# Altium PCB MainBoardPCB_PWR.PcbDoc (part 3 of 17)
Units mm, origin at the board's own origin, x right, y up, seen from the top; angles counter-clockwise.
Board outline 333.63 x 349.38 mm, 16 copper layers (L1, L2 (GND), L3 (Sign), L4 (GND), L5 (Sign), L6 (PWR/GND), L7(PWR/GND), L8 (PWR/GND), L9 (PWR/GND), L10 (PWR/GND), L11 (PWR/GND), L12 (Sign), L13 (GND), L14 (Sign), L15 (GND), L16), stack 2.503 mm thick; 2187 components, 1615 nets, 7987 pads, 1695 vias.
Unrouted connection lines stored in the file: 4757.
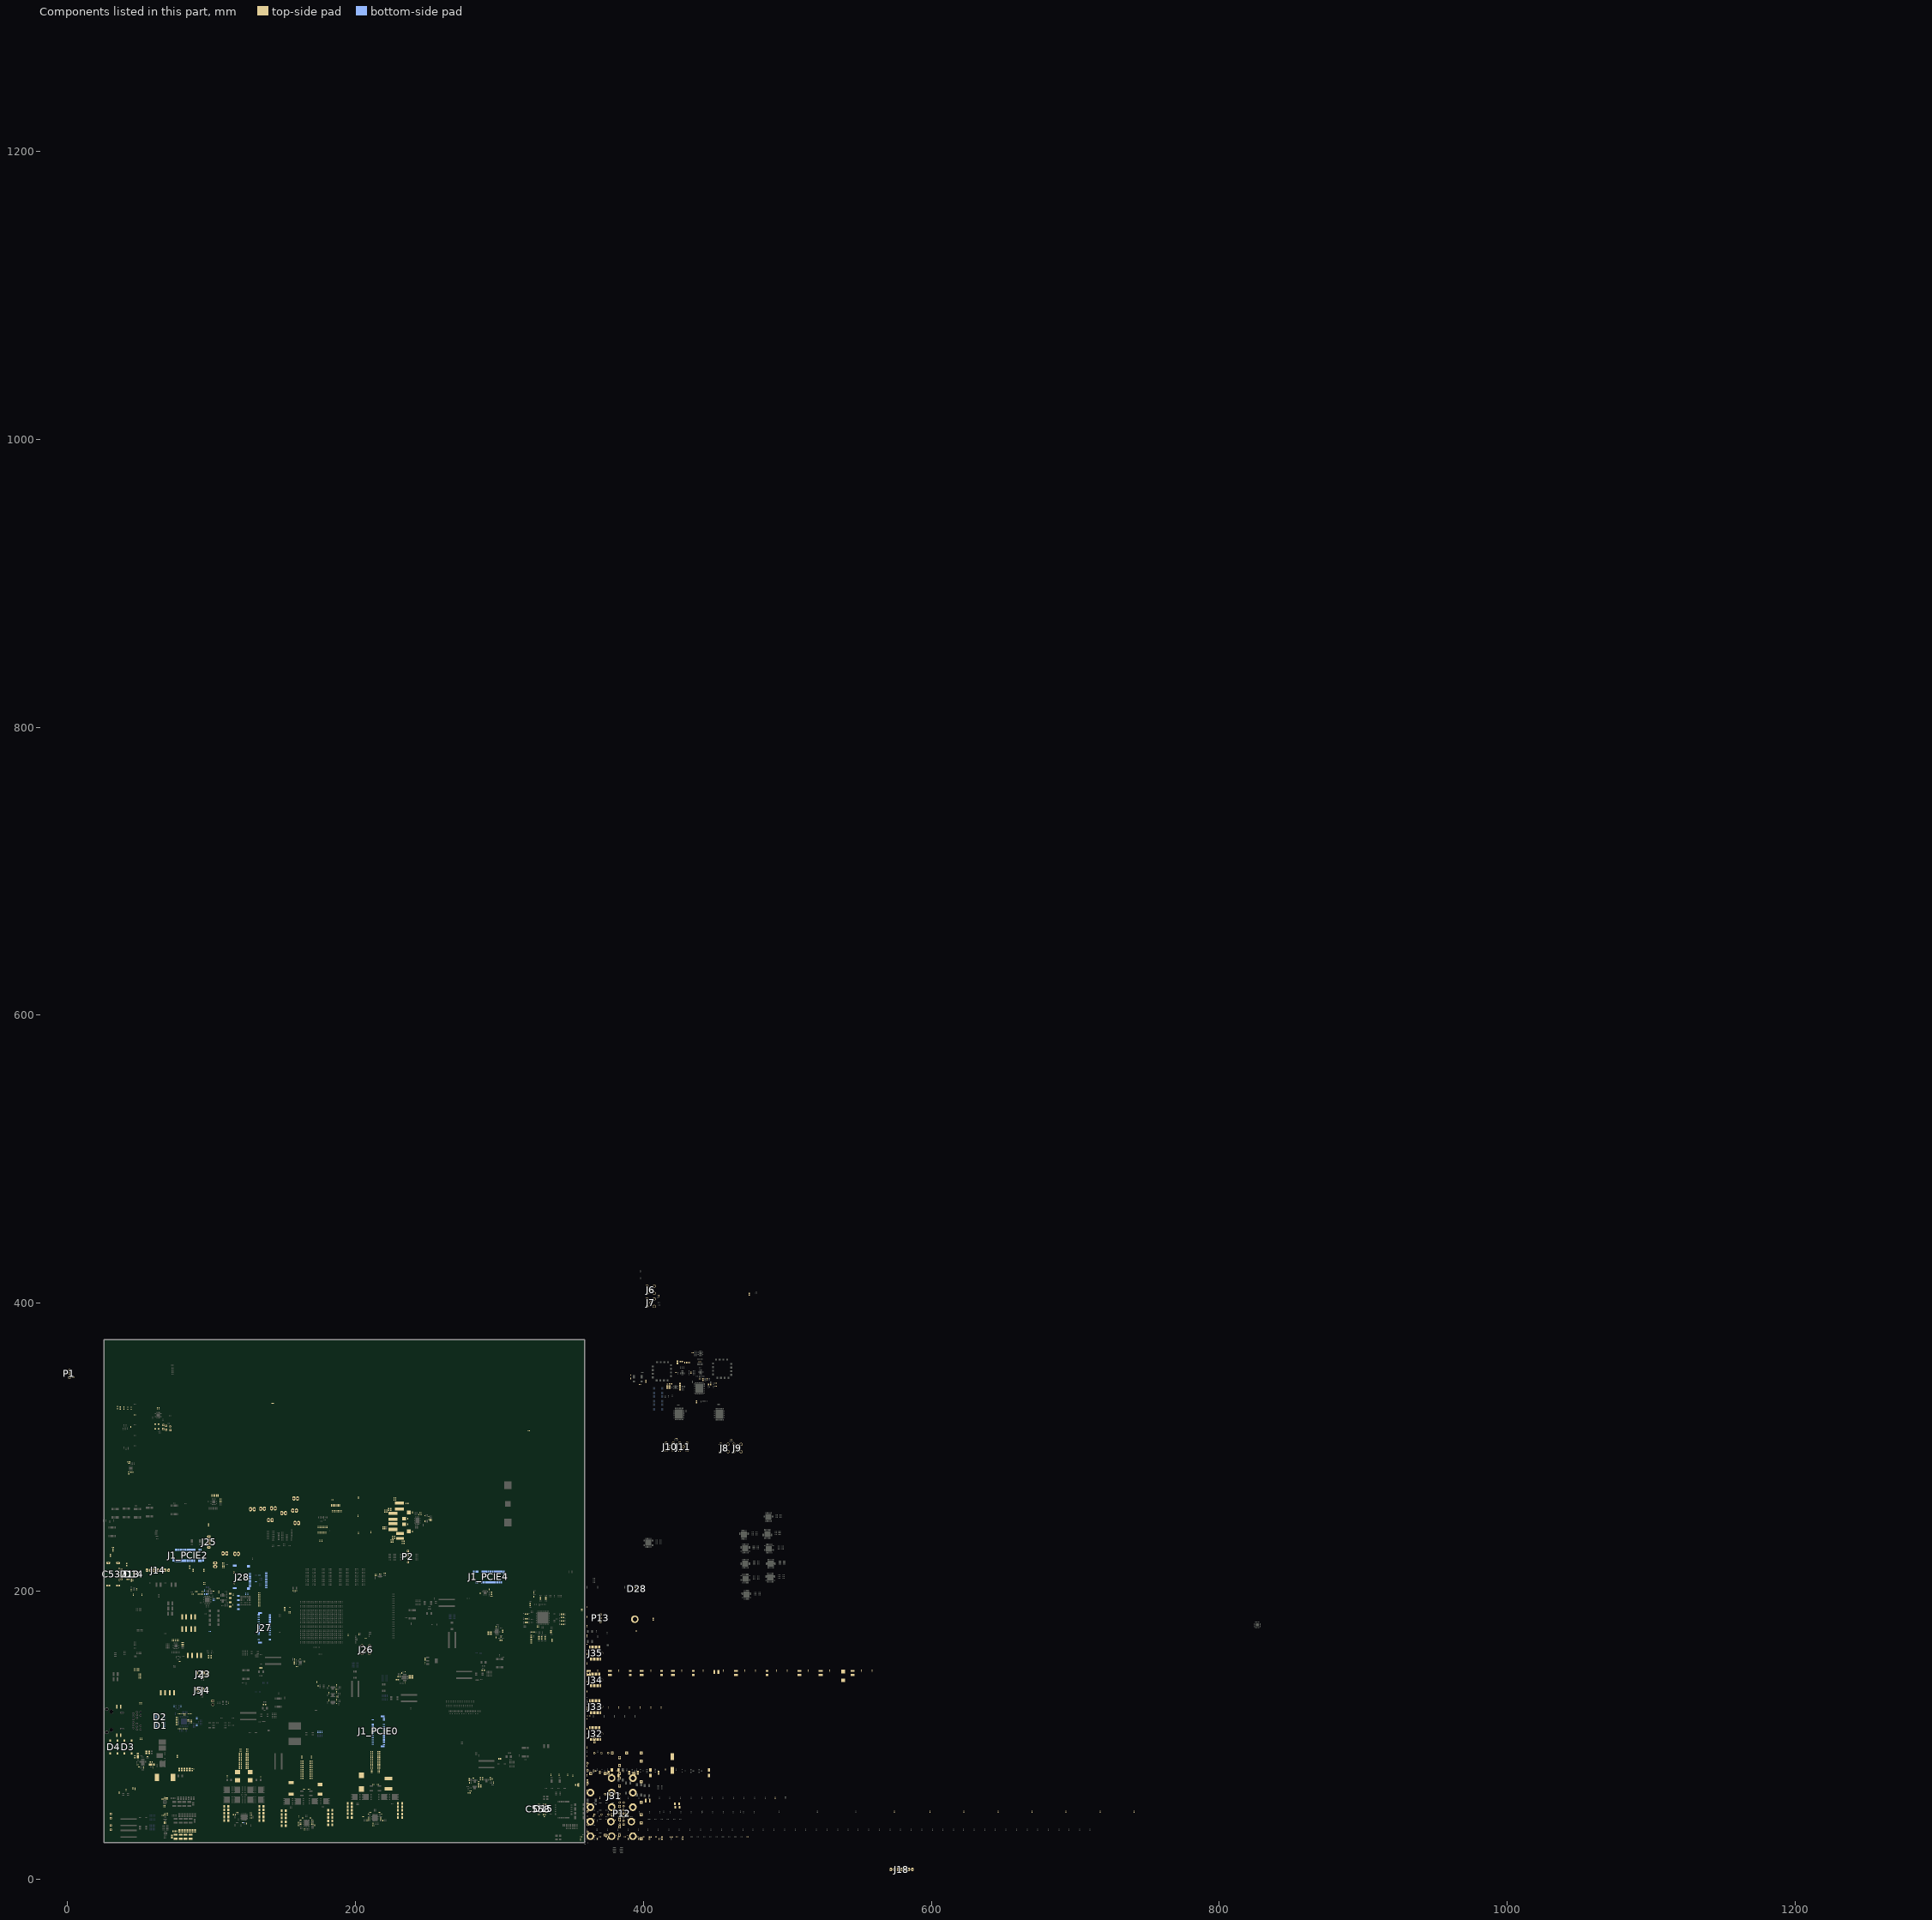
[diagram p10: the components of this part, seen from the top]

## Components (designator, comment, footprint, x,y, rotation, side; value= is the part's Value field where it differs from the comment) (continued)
C309_U_Pomiar_pradu_napiecia_2 "100nF" "CAP 0402/1005 RF" 360.832,130.327 r90 top (schematic designator C309)
C309_U_Pomiar_pradu_napiecia_3 "100nF" "CAP 0402/1005 RF" 360.832,136.804 r90 top (schematic designator C309)
C309_U_Pomiar_pradu_napiecia_4 "100nF" "CAP 0402/1005 RF" 360.832,143.281 r90 top (schematic designator C309)
C309_U_Pomiar_pradu_napiecia_5 "100nF" "CAP 0402/1005 RF" 360.832,149.758 r90 top (schematic designator C309)
C309_U_Pomiar_pradu_napiecia_6 "100nF" "CAP 0402/1005 RF" 360.832,156.235 r90 top (schematic designator C309)
C309_U_Pomiar_pradu_napiecia_7 "100nF" "CAP 0402/1005 RF" 360.832,162.712 r90 top (schematic designator C309)
C309_U_Pomiar_pradu_napiecia_8 "100nF" "CAP 0402/1005 RF" 360.832,169.189 r90 top (schematic designator C309)
C309_U_Pomiar_pradu_napiecia_9 "100nF" "CAP 0402/1005 RF" 360.832,175.666 r90 top (schematic designator C309)
C309_U_Pomiar_pradu_napiecia_10 "100nF" "CAP 0402/1005 RF" 360.832,182.143 r90 top (schematic designator C309)
C309_U_Pomiar_pradu_napiecia_11 "100nF" "CAP 0402/1005 RF" 360.832,188.62 r90 top (schematic designator C309)
C310 "100nF" "CAP 0402/1005 RF" 360.832,40.386 r90 top
C311_I2C_Expander1 "1uF" "CAP 0402/1005 RF" 360.832,52.603 r90 top (schematic designator C311)
C311_I2C_Expander2 "1uF" "CAP 0402/1005 RF" 360.832,59.08 r90 top (schematic designator C311)
C311_I2C_Expander3 "1uF" "CAP 0402/1005 RF" 360.832,65.557 r90 top (schematic designator C311)
C311_I2C_Expander? "1uF" "CAP 0402/1005 RF" 360.832,72.034 r90 top (schematic designator C311)
C311_I2C_Expander_10 "1uF" "CAP 0402/1005 RF" 360.832,78.511 r90 top (schematic designator C311)
C311_I2C_Expander_11 "1uF" "CAP 0402/1005 RF" 360.832,84.988 r90 top (schematic designator C311)
C311_I2C_Expander_12 "1uF" "CAP 0402/1005 RF" 360.832,91.465 r90 top (schematic designator C311)
C311_I2C_Expander_13 "1uF" "CAP 0402/1005 RF" 360.832,97.942 r90 top (schematic designator C311)
C311_I2C_Expander_14 "1uF" "CAP 0402/1005 RF" 360.832,104.419 r90 top (schematic designator C311)
C311_I2C_Expander_15 "1uF" "CAP 0402/1005 RF" 360.832,110.896 r90 top (schematic designator C311)
C311_I2C_Expander_16 "1uF" "CAP 0402/1005 RF" 360.832,117.373 r90 top (schematic designator C311)
C320 "10nF" "CAP 0402/1005 RF" 397.535,343.662 r180 top
C321 "3.3nF" "CAP 0603/1608 RF" 401.726,345.77 r90 top
C322 "27pF" "CAP 0402/1005 RF" 391.185,347.749 r90 top
C323 "27pF" "CAP 0402/1005 RF" 391.185,349.729 r270 top
C324 "10uF" "CAP 0805/2012 RF" 354.8,65.363 r90 top
C325 "100nF" "CAP 0402/1005 RF" 439.853,359.673 r270 top
C326 "1uF" "CAP 0402/1005 RF" 335.672,72.451 r90 top
C327 "1uF" "CAP 0402/1005 RF" 341.514,72.451 r90 top
C328 "1uF" "CAP 0402/1005 RF" 347.356,72.451 r90 top
C329 "1uF" "CAP 0402/1005 RF" 350.97,71.756 r90 top
C330 "100nF" "CAP 0402/1005 RF" 438.652,359.673 r270 top
C331 "1uF" "CAP 0402/1005 RF" 202.311,170.148 r270 top
C332 "1uF" "CAP 0402/1005 RF" 207.098,167.219 r0 top
C333 "10nF" "CAP 0201/0603 RF" 422.687,351.917 r180 top
C334 "100nF" "CAP 0402/1005 RF" 450.24,344.378 r180 top
C335 "100nF" "CAP 0402/1005 RF" 450.24,342.288 r180 top
C336 "100nF" "CAP 0402/1005 RF" 429.836,358.766 r90 top
C337 "100nF" "CAP 0402/1005 RF" 430.894,358.766 r90 top
C338 "100nF" "CAP 0402/1005 RF" 431.952,358.766 r90 top
C339 "10uF" "CAP 0805/2012 RF" 423.697,358.837 r90 top
C340 "1uF" "CAP 0402/1005 RF" 428.777,358.766 r90 top
C341 "100nF" "CAP 0402/1005 RF" 434.229,365.633 r0 top
C342 "100nF" "CAP 0402/1005 RF" 433.222,351.253 r0 top
C343 "100nF" "CAP 0402/1005 RF" 433.222,352.253 r0 top
C344 "10nF" "CAP 0201/0603 RF" 422.687,350.832 r180 top
C345 "22pF" "CAP 0402/1005 RF" 118.036,44.404 r0 top
C346 "100nF" "CAP 0402/1005 RF" 118.036,46.421 r180 top
C347 "10uF" "CAP 1206/3216" 110.249,48.133 r180 top
C348 "10uF" "CAP 1206/3216" 110.249,50.597 r180 top
C349 "22pF" "CAP 0402/1005 RF" 127.419,44.139 r180 top
C350 "100nF" "CAP 0402/1005 RF" 127.404,46.156 r0 top
C351 "1uF" "CAP 0402/1005 RF" 121.352,38.84 r90 top
C352 "10uF" "CAP 1206/3216" 134.685,48.088 r0 top
C353 "10uF" "CAP 1206/3216" 134.685,50.597 r0 top
C354 "4.7 µF" "CAP 0603/1608 RF" 220.396,243.898 r270 top
C355 "4.7 µF" "CAP 0603/1608 RF" 219.102,243.909 r270 top
C356 "1uF" "CAP 0402/1005 RF" 124.277,38.625 r90 top
C357 "100nF" "CAP 0402/1005 RF" 127.419,42.524 r180 top
C358 "1uF" "CAP 0603/1608 RF" 115.967,44.623 r0 top
C359 "100nF" "CAP 0402/1005 RF" 124.878,90.408 r0 top
C360 "470nF" "CAP 0402/1005 RF" 120.127,90.408 r180 top
C361 "1uF" "CAP 0402/1005 RF" 124.879,88.519 r0 top
C362 "4.7uF" "CAP 0603/1608 RF" 120.127,79.465 r180 top
C363 "10uF" "CAP 0603/1608 RF" 120.127,78.146 r180 top
C364 "22uF" "CAP 0603/1608 RF" 120.127,80.785 r180 top
C365 "10uF" "CAP 0603/1608 RF" 124.879,76.826 r0 top
C366 "22uF" "CAP 0603/1608 RF" 120.127,76.826 r180 top
C367 "10uF" "CAP 0603/1608 RF" 124.879,79.465 r0 top
C368 "22uF" "CAP 0603/1608 RF" 124.879,78.146 r0 top
C369 "10uF" "CAP 0603/1608 RF" 124.879,80.785 r0 top
C370 "22uF" "CAP 0603/1608 RF" 120.127,82.104 r180 top
C371 "10uF" "CAP 1206/3216 - 0.8MM" 134.685,43.216 r0 top
C372 "10uF" "CAP 1206/3216 - 0.8MM" 110.249,45.669 r180 top
C373 "10uF" "CAP 1206/3216 - 0.8MM" 110.249,40.767 r180 top
C374 "10uF" "CAP 1206/3216 - 0.8MM" 134.685,45.669 r0 top
C375 "10uF" "CAP 1206/3216 - 0.8MM" 110.249,43.216 r180 top
C376 "10uF" "CAP 1206/3216 - 0.8MM" 134.685,40.706 r0 top
C377 "100nF" "CAP 0402/1005 RF" 124.878,89.449 r0 top
C378 "470nF" "CAP 0402/1005 RF" 120.128,88.519 r180 top
C379 "1uF" "CAP 0402/1005 RF" 120.127,89.449 r180 top
C380 "4.7uF" "CAP 0603/1608 RF" 120.127,83.424 r180 top
C381 "10uF" "CAP 0603/1608 RF" 124.879,83.424 r0 top
C382 "22uF" "CAP 0603/1608 RF" 124.879,84.743 r0 top
C383 "10uF" "CAP 0603/1608 RF" 120.127,87.382 r180 top
C384 "22uF" "CAP 0603/1608 RF" 124.879,86.063 r0 top
C385 "10uF" "CAP 0603/1608 RF" 124.879,82.104 r0 top
C386 "22uF" "CAP 0603/1608 RF" 120.127,84.743 r180 top
C387 "10uF" "CAP 0603/1608 RF" 124.878,87.382 r0 top
C388 "22uF" "CAP 0603/1608 RF" 120.127,86.063 r180 top
C389 "22pF" "CAP 0402/1005 RF" 208.951,44.8 r270 top
C390 "100nF" "CAP 0402/1005 RF" 210.306,46.316 r180 top
C391 "10uF" "CAP 1206/3216" 196.063,50.291 r180 top
C392 "10uF" "CAP 1206/3216" 196.063,52.731 r0 top
C393 "22pF" "CAP 0402/1005 RF" 218.055,44.799 r270 top
C394 "100nF" "CAP 0402/1005 RF" 216.655,46.316 r0 top
C395 "1uF" "CAP 0402/1005 RF" 212.42,36.998 r0 top
C396 "10uF" "CAP 1206/3216" 231.006,50.198 r180 top
C397 "10uF" "CAP 1206/3216" 231.006,52.687 r0 top
C398 "1uF" "CAP 0402/1005 RF" 212.295,38.616 r90 top
C399 "100nF" "CAP 0402/1005 RF" 205.386,43.462 r180 top
C400 "10uF" "CAP 1206/3216 - 0.8MM" 231.007,42.723 r180 top
C401 "10uF" "CAP 1206/3216 - 0.8MM" 231.007,45.203 r180 top
C402 "10uF" "CAP 1206/3216 - 0.8MM" 231.007,47.72 r180 top
C403 "10uF" "CAP 1206/3216 - 0.8MM" 196.032,42.803 r0 top
C404 "10uF" "CAP 1206/3216 - 0.8MM" 196.063,45.323 r0 top
C405 "10uF" "CAP 1206/3216 - 0.8MM" 196.063,47.846 r0 top
C406 "100nF" "CAP 0402/1005 RF" 211.318,73.946 r180 top
C407 "470nF" "CAP 0402/1005 RF" 211.321,74.92 r180 top
C408 "1uF" "CAP 0402/1005 RF" 211.318,75.891 r180 top
C409 "4.7uF" "CAP 0603/1608 RF" 211.321,79.974 r180 top
C410 "10uF" "CAP 0603/1608 RF" 211.321,81.397 r180 top
C411 "22uF" "CAP 0603/1608 RF" 211.321,77.155 r180 top
C412 "10uF" "CAP 0603/1608 RF" 211.321,78.552 r180 top
C413 "22uF" "CAP 0603/1608 RF" 211.321,82.794 r180 top
C414 "10uF" "CAP 0603/1608 RF" 211.321,87.036 r180 top
C415 "22uF" "CAP 0603/1608 RF" 211.321,88.458 r180 top
C416 "10uF" "CAP 0603/1608 RF" 211.321,84.191 r180 top
C417 "22uF" "CAP 0603/1608 RF" 211.318,85.626 r180 top
C418 "100nF" "CAP 0402/1005 RF" 216.235,73.946 r0 top
C419 "470nF" "CAP 0402/1005 RF" 216.235,74.92 r0 top
C420 "1uF" "CAP 0402/1005 RF" 216.235,75.891 r0 top
C421 "4.7uF" "CAP 0603/1608 RF" 216.236,79.974 r0 top
C422 "10uF" "CAP 0603/1608 RF" 216.236,81.397 r0 top
C423 "22uF" "CAP 0603/1608 RF" 216.235,77.155 r0 top
C424 "10uF" "CAP 0603/1608 RF" 216.236,78.552 r0 top
C425 "22uF" "CAP 0603/1608 RF" 216.236,82.794 r0 top
C426 "10uF" "CAP 0603/1608 RF" 216.237,87.036 r0 top
C427 "22uF" "CAP 0603/1608 RF" 216.227,88.453 r0 top
C428 "10uF" "CAP 0603/1608 RF" 216.236,84.191 r0 top
C429 "22uF" "CAP 0603/1608 RF" 216.236,85.626 r0 top
C430 "22pF" "CAP 0402/1005 RF" 161.858,41.04 r0 top
C431 "100nF" "CAP 0402/1005 RF" 163.383,42.453 r90 top
C432 "10uF" "CAP 1206/3216" 150.151,44.958 r180 top
C433 "10uF" "CAP 1206/3216" 150.151,47.523 r0 top
C434 "22pF" "CAP 0402/1005 RF" 170.124,40.64 r180 top
C435 "100nF" "CAP 0402/1005 RF" 168.633,42.468 r90 top
C436 "1uF" "CAP 0402/1005 RF" 160.318,39.203 r270 top
C437 "10uF" "CAP 1206/3216" 182.534,45.266 r180 top
C438 "10uF" "CAP 1206/3216" 182.534,47.806 r0 top
C439 "1uF" "CAP 0402/1005 RF" 164.433,34.527 r90 top
C440 "100nF" "CAP 0402/1005 RF" 160.538,43.517 r90 top
C441 "10uF" "CAP 1206/3216 - 0.8MM" 182.534,37.765 r180 top
C442 "10uF" "CAP 1206/3216 - 0.8MM" 182.524,40.248 r180 top
C443 "10uF" "CAP 1206/3216 - 0.8MM" 182.534,42.726 r180 top
C444 "10uF" "CAP 1206/3216 - 0.8MM" 150.151,37.187 r0 top
C445 "10uF" "CAP 1206/3216 - 0.8MM" 150.151,39.767 r0 top
C446 "10uF" "CAP 1206/3216 - 0.8MM" 150.151,42.367 r0 top
C447 "100nF" "CAP 0402/1005 RF" 162.815,85.322 r180 top
C448 "470nF" "CAP 0402/1005 RF" 162.815,84.205 r180 top
C449 "1uF" "CAP 0402/1005 RF" 162.815,83.112 r180 top
C450 "4.7uF" "CAP 0603/1608 RF" 162.815,81.817 r180 top
C451 "10uF" "CAP 0603/1608 RF" 162.815,80.318 r180 top
C452 "22uF" "CAP 0603/1608 RF" 162.816,78.845 r180 top
C453 "10uF" "CAP 0603/1608 RF" 162.816,77.372 r180 top
C454 "22uF" "CAP 0603/1608 RF" 162.816,75.899 r180 top
C455 "10uF" "CAP 0603/1608 RF" 162.816,74.426 r180 top
C456 "22uF" "CAP 0603/1608 RF" 162.816,72.952 r180 top
C457 "10uF" "CAP 0603/1608 RF" 162.816,71.479 r180 top
C458 "22uF" "CAP 0603/1608 RF" 162.816,70.006 r180 top
C459 "100nF" "CAP 0402/1005 RF" 169.283,85.322 r0 top
C460 "470nF" "CAP 0402/1005 RF" 169.282,84.204 r0 top
C461 "1uF" "CAP 0402/1005 RF" 169.282,83.112 r0 top
C462 "4.7uF" "CAP 0603/1608 RF" 169.282,81.817 r0 top
C463 "10uF" "CAP 0603/1608 RF" 169.282,80.318 r0 top
C464 "22uF" "CAP 0603/1608 RF" 169.266,78.845 r0 top
C465 "10uF" "CAP 0603/1608 RF" 169.282,77.372 r0 top
C466 "22uF" "CAP 0603/1608 RF" 169.282,75.899 r0 top
C467 "10uF" "CAP 0603/1608 RF" 169.281,74.425 r0 top
C468 "22uF" "CAP 0603/1608 RF" 169.281,72.952 r0 top
C469 "10uF" "CAP 0603/1608 RF" 169.281,71.479 r0 top
C470 "22uF" "CAP 0603/1608 RF" 169.281,70.006 r0 top
C471 "100nF" "CAP 0402/1005 RF" 51.689,97.4 r90 top
C472 "100nF" "CAP 0402/1005 RF" 50.546,97.409 r90 top
C473 "100nF" "CAP 0402/1005 RF" 50.292,122.183 r270 top
C474 "100nF" "CAP 0402/1005 RF" 51.308,122.183 r270 top
C475 "Capacitor_1210" CAPC3326X17L 35.636,99.915 r180 top
C476 "Capacitor_1210" CAPC3326X17L 35.636,119.761 r180 top
C479 "100nF" "CAP 0402/1005 RF" 89.798,107.315 r180 bottom
C480 "27pF" "CAP 0402/1005 RF" 78.809,120.113 r270 bottom
C481 "27pF" "CAP 0402/1005 RF" 74.11,120.113 r90 bottom
C482 "100nF" "CAP 0402/1005 RF" 89.798,106.365 r180 bottom
C483 "100nF" "CAP 0402/1005 RF" 89.798,112.141 r180 bottom
C484 "100nF" "CAP 0402/1005 RF" 89.798,111.141 r180 bottom
C485 "1uF" "CAP 0402/1005 RF" 78.914,104.752 r90 top
C486 "1uF" "CAP 0402/1005 RF" 78.911,114.466 r270 top
C487 "100nF" "CAP 0402/1005 RF" 77.937,114.466 r270 top
C488 "100nF" "CAP 0402/1005 RF" 76.966,114.466 r270 top
C489 "10uF" "CAP 0402/1005 RF" 77.937,104.752 r90 top
C490 "10nF" "CAP 0402/1005 RF" 76.99,104.752 r90 top
C491 "1uF" "CAP 0402/1005 RF" 83.828,109.639 r0 top
C492 "1uF" "CAP 0402/1005 RF" 83.837,110.561 r0 top
C493 "1uF" "CAP 0402/1005 RF" 173.197,136.909 r90 top
C494 "100nF" "CAP 0402/1005 RF" 81.837,114.46 r270 top
C495 "100nF" "CAP 0402/1005 RF" 79.902,114.466 r270 top
C496 "100nF" "CAP 0402/1005 RF" 80.87,114.46 r270 top
C497 "10uF" "CAP 0402/1005 RF" 83.038,104.752 r90 top
C498 "10nF" "CAP 0402/1005 RF" 82.107,104.752 r90 top
C499 "1uF" "CAP 0402/1005 RF" 75.941,111.541 r0 top
C500 "1uF" "CAP 0402/1005 RF" 75.932,106.045 r0 top
C501 "100nF" "CAP 0402/1005 RF" 75.932,106.965 r0 top
C502 "100nF" "CAP 0402/1005 RF" 75.932,110.639 r0 top
C503 "10uF" "CAP 0402/1005 RF" 75.941,112.443 r0 top
C504 "10nF" "CAP 0402/1005 RF" 75.932,107.893 r0 top
C505 "1uF" "CAP 0402/1005 RF" 80.217,104.752 r90 top
C506 "1uF" "CAP 0402/1005 RF" 75.932,108.809 r0 top
C507 "1uF" "CAP 0402/1005 RF" 85.001,114.466 r270 top
C508 "1uF" "CAP 0402/1005 RF" 85.761,108.639 r180 top
C509 "100nF" "CAP 0402/1005 RF" 85.741,109.542 r180 top
C510 "100nF" "CAP 0402/1005 RF" 83.992,114.466 r270 top
C511 "100nF" "CAP 0402/1005 RF" 75.932,109.724 r0 top
C512 "100nF" "CAP 0402/1005 RF" 86.011,114.466 r270 top
C513 "10uF" "CAP 0402/1005 RF" 81.14,104.752 r90 top
C514 "10nF" "CAP 0402/1005 RF" 85.741,110.444 r180 top
C515 "4.7uF" "CAP 0603/1608 RF" 104.604,195.232 r0 top
C516 "4.7uF" "CAP 0603/1608 RF" 105.054,199.396 r270 top
C517 "100nF" "CAP 0402/1005 RF" 115.249,197.535 r90 top
C518 "2.2uF" "CAP 1206/3216 - 0.8MM" 118.72,195.199 r90 bottom
C519 "100nF" "CAP 0402/1005 RF" 114.989,190.479 r270 top
C520 "2.2uF" "CAP 1206/3216 - 0.8MM" 118.72,188.994 r90 bottom
C521 "100nF" "CAP 0402/1005 RF" 125.318,198.013 r270 bottom
C522 "1uF" "CAP 0402/1005 RF" 123.76,198.013 r270 bottom
C523 "4.7uF" "CAP 0603/1608 RF" 87.249,214.503 r90 top
C524 "4.7uF" "CAP 0603/1608 RF" 94.742,214.503 r90 top
C525 "10nF" "CAP 0402/1005 RF" 150.885,188.731 r180 top
C526 "10nF" "CAP 0402/1005 RF" 150.885,187.72 r180 top
C527 "10nF" "CAP 0402/1005 RF" 154.323,184.707 r180 top
C528 "10nF" "CAP 0402/1005 RF" 154.323,185.801 r180 top
C529 "10nF" "CAP 0402/1005 RF" 154.305,188.341 r270 top
C530 "10nF" "CAP 0402/1005 RF" 150.885,186.577 r180 top
C531 "100nF" "CAP 0402/1005 RF" 46.736,322.453 r180 top
C532 "100nF" "CAP 0402/1005 RF" 63.5,327.076 r90 top
C533 "100nF" "CAP 0402/1005 RF" 62.4,327.076 r90 top
C534 "100nF" "CAP 0402/1005 RF" 44,314.013 r270 top
C535 "22pF" "CAP 0402/1005 RF" 157.014,200.432 r180 top
C536 "22pF" "CAP 0402/1005 RF" 158.734,200.432 r0 top
C537 "WE-Communication Connectors 692121130100" 692121130100 35.121,203.883 r270 top
C538 "1uF" "CAP 0402/1005 RF" 45.547,207.532 r90 top
C539 "4.7uF" "CAP 0603/1608 RF" 44.348,207.532 r90 top
C540 "100nF" "CAP 0402/1005 RF" 31.669,230.378 r0 top
C541 "100nF" "CAP 0402/1005 RF" 31.796,229.489 r0 top
C542 "100nF" "CAP 0402/1005 RF" 31.796,228.6 r0 top
C543 "100nF" "CAP 0402/1005 RF" 31.796,227.711 r0 top
C544 "1uF" "CAP 0402/1005 RF" 133.341,211.033 r180 bottom
C545 "100nF" "CAP 0402/1005 RF" 357.251,187.579 r0 top
C546 "100nF" "CAP 0402/1005 RF" 357.251,186.69 r0 top
C547 "100nF" "CAP 0402/1005 RF" 130.946,206.629 r0 bottom
C548 "11pF" "CAP 0402/1005 RF" 161.859,38.015 r0 top
C549 "220pF" "CAP 0402/1005 RF" 160.268,37.4 r270 top
C550 "4.7uF" "CAP 0402/1005 RF" 181.639,133.844 r270 top
C551 "10uF" "CAP 0402/1005 RF" 186.791,134.644 r270 top
C552 "4.7uF" "CAP 0402/1005 RF" 181.639,129.204 r270 top
C553 "10uF" "CAP 0402/1005 RF" 186.869,129.833 r270 top
C554 "4.7uF" "CAP 0402/1005 RF" 181.639,124.215 r270 top
C555 "10uF" "CAP 0402/1005 RF" 186.854,124.45 r270 top
C558 "WR-Communication Connectors 614105150721" 614105150721 327.441,48.431 r90 bottom
C559 "1uF" "CAP 0402/1005 RF" 331.387,43.48 r0 top
C560 "4.7uF" "CAP 0603/1608 RF" 331.26,44.75 r0 top
C561 "100nF" "CAP 0402/1005 RF" 77.861,151.16 r0 top
C562 "100nF" "CAP 0402/1005 RF" 395.088,172.212 r0 top
C563_5V_to_3V3_for_FTDI "4.7uF" "CAP 0603/1608 RF" 42.745,282.16 r90 top (schematic designator C563)
C563_U_5V_to_3V31 "4.7uF" "CAP 0603/1608 RF" 406.908,180.457 r90 top (schematic designator C563)
C563_U_5V_to_3V32 "4.7uF" "CAP 0603/1608 RF" 287.029,64.684 r270 top (schematic designator C563)
C563_U_5V_to_3V33 "4.7uF" "CAP 0603/1608 RF" 286.906,69.606 r270 top (schematic designator C563)
C564_5V_to_3V3_for_FTDI "4.7uF" "CAP 0603/1608 RF" 44.82,282.785 r180 top (schematic designator C564)
C564_U_5V_to_3V31 "4.7uF" "CAP 0603/1608 RF" 285.672,67.109 r90 top (schematic designator C564)
C564_U_5V_to_3V32 "4.7uF" "CAP 0603/1608 RF" 285.654,64.684 r270 top (schematic designator C564)
C564_U_5V_to_3V33 "4.7uF" "CAP 0603/1608 RF" 288.308,69.606 r270 top (schematic designator C564)
C565_5V_to_3V3_for_FTDI "4.7uF" "CAP 0603/1608 RF" 42.52,289.909 r0 top (schematic designator C565)
C565_U_5V_to_3V31 "4.7uF" "CAP 0603/1608 RF" 279.018,69.134 r90 top (schematic designator C565)
C565_U_5V_to_3V32 "4.7uF" "CAP 0603/1608 RF" 278.954,59.976 r180 top (schematic designator C565)
C565_U_5V_to_3V33 "4.7uF" "CAP 0603/1608 RF" 293.804,69.606 r270 top (schematic designator C565)
C566_5V_to_3V3_for_FTDI "100nF" "CAP 0402/1005 RF" 42.745,287.706 r0 top (schematic designator C566)
C566_U_5V_to_3V31 "100nF" "CAP 0402/1005 RF" 279.242,66.899 r270 top (schematic designator C566)
C566_U_5V_to_3V32 "100nF" "CAP 0402/1005 RF" 280.366,61.582 r90 top (schematic designator C566)
C566_U_5V_to_3V33 "100nF" "CAP 0402/1005 RF" 295.76,67.053 r90 top (schematic designator C566)
C567_5V_to_3V3_for_FTDI "2.2uF" "CAP 0402/1005 RF" 42.772,288.686 r0 top (schematic designator C567)
C567_U_5V_to_3V31 "2.2uF" "CAP 0402/1005 RF" 281.861,70.159 r180 top (schematic designator C567)
C567_U_5V_to_3V32 "2.2uF" "CAP 0402/1005 RF" 279.451,61.582 r90 top (schematic designator C567)
C567_U_5V_to_3V33 "2.2uF" "CAP 0402/1005 RF" 294.937,69.521 r270 top (schematic designator C567)
C568 "4.7uF" "CAP 0402/1005 RF" 292.935,201.182 r270 top
C569 "4.7uF" "CAP 0402/1005 RF" 294.485,196.36 r0 top
C570 "4.7uF" "CAP 0402/1005 RF" 286.714,198.556 r90 top
C571 "1nF" "CAP 0201/0603 RF" 290.33,196.303 r180 top
C572 "10uF" "CAP 0603/1608 RF" 229.012,138.456 r0 top
C573 "10nF" "CAP 0201/0603 RF" 231.66,136.949 r180 top
C574 "10uF" "CAP 0805/2012 RF" 237.691,140.38 r270 top
C575 "10uF" "CAP 0805/2012 RF" 239.494,140.38 r270 top
C576 "10uF" "CAP 0603/1608 RF" 230.305,140.553 r0 top
C577 "10nF" "CAP 0201/0603 RF" 232.192,143.112 r270 top
C578 "100nF" "CAP 0402/1005 RF" 234.68,143.658 r270 top
C579 "100nF" "CAP 0402/1005 RF" 234.692,136.374 r90 top
C580 "4.7uF" "CAP 0805/2012 RF" 425.358,343.392 r270 top
C581 "10uF" "CAP 0805/2012 RF" 416.436,341.692 r90 top
C582 "4.7uF" "CAP 0805/2012 RF" 418.189,341.692 r90 top
C583 "100nF" "CAP 0402/1005 RF" 416.436,343.829 r0 top
C584 "4.7uF" "CAP 0805/2012 RF" 425.358,340.592 r90 top
C585 "100nF" "CAP 0402/1005 RF" 111.695,122.453 r90 top
C586 "2.2uF" "CAP 1206/3216 - 0.8MM" 113.084,196.76 r90 top
C587 "2.2uF" "CAP 1206/3216 - 0.8MM" 113.084,190.759 r270 top
C588 "100nF" "CAP 0402/1005 RF" 323.853,198.975 r270 top
C589 "100nF" "CAP 0402/1005 RF" 323.853,196.112 r270 top
C590 "100nF" "CAP 0402/1005 RF" 322.084,169.216 r0 top
C591 "10uF" "CAP 0402/1005 RF" 322.084,165.152 r0 top
C592 "100nF" "CAP 0402/1005 RF" 322.084,164.067 r0 top
C593 "100nF" "CAP 0402/1005 RF" 326.139,175.429 r90 top
C594 "100nF" "CAP 0402/1005 RF" 327.063,175.429 r90 top
C595 "10uF" "CAP 0805/2012 RF" 56.704,88.017 r270 top
C596 "10uF" "CAP 0805/2012 RF" 54.875,88.007 r270 top
C597 "1uF" "CAP 0402/1005 RF" 55.54,84.951 r180 top
C598 "10uF" "CAP 0603/1608 RF" 58.228,81.386 r180 top
C603 "43pF" "CAP 0201/0603 RF" 250.98,249.474 r270 top
C604 "1µF" "CAP 0402/1005 RF" 245.124,254.516 r180 top
C605 "100pF" "CAP 0201/0603 RF" 250.972,251.571 r90 top
C606 "4.7 µF" "CAP 0603/1608 RF" 220.471,255.655 r270 top
C607 "4.7 µF" "CAP 0603/1608 RF" 224.596,256.791 r270 top
C609 "FC0H224ZFTBR24" FC0H224ZFTBR24 420.04,80.314 r90 top
C610 "4.7 µF" "CAP 0603/1608 RF" 223.201,256.791 r270 top
C611 "4.7 µF" "CAP 0603/1608 RF" 221.799,255.655 r270 top
C612 "43pF" "CAP 0201/0603 RF" 248.17,252.624 r90 top
C613 "4.7 µF" "CAP 0603/1608 RF" 227.389,264.63 r0 top
C614 "4.7 µF" "CAP 0603/1608 RF" 235.772,260.761 r180 top
C615 "4.7 µF" "CAP 0603/1608 RF" 227.389,263.314 r0 top
C616 "100pF" "CAP 0201/0603 RF" 248.32,248.558 r270 top
C617 "4.7 µF" "CAP 0603/1608 RF" 225.383,235.476 r0 top
C618 "4.7 µF" "CAP 0603/1608 RF" 233.121,233.286 r180 top
C619 "4.7 µF" "CAP 0603/1608 RF" 225.875,237.479 r270 top
C620 "4.7 µF" "CAP 0603/1608 RF" 233.121,234.614 r180 top
C621 "4.7 µF" "CAP 0603/1608 RF" 227.265,237.479 r270 top
C622 "4.7 µF" "CAP 0603/1608 RF" 225.396,234.202 r0 top
C623 "100nF" "CAP 0402/1005 RF" 387.198,43.485 r0 top
C624 "10nF" "CAP 0201/0603 RF" 360.934,43.637 r0 top
C625 "10nF" "CAP 0201/0603 RF" 365.252,43.637 r0 top
C626 "10nF" "CAP 0201/0603 RF" 369.57,43.637 r0 top
C627 "100nF" "CAP 0201/0603 RF" 360.68,158.648 r90 top
C628 "470nF" "CAP 0402/1005 RF" 368.198,158.318 r90 top
C629 "100nF" "CAP 0201/0603 RF" 381.241,75.298 r0 top
C630 "470nF" "CAP 0402/1005 RF" 385.889,75.146 r0 top
C631 "10uF" "CAP 0603/1608 RF" 365.9,74.968 r0 top
C632 "470nF" "CAP 0402/1005 RF" 361.251,75.146 r0 top
C633 "3nF" "CAP 0402/1005 RF" 110.833,71.526 r270 top
C634 "330pF" "CAP 0402/1005 RF" 122.002,39.112 r0 bottom
C635 "6.8nF" "CAP 0402/1005 RF" 122.002,38.147 r0 bottom
C636 "3nF" "CAP 0402/1005 RF" 134.085,71.416 r270 top
C637 "1.2nF" "CAP 0402/1005 RF" 212.33,65.623 r180 top
C638 "1.2nF" "CAP 0402/1005 RF" 215.56,65.623 r0 top
C639 "47nF" "CAP 0402/1005 RF" 209.441,42.359 r0 top
C640 "47nF" "CAP 0402/1005 RF" 217.555,42.359 r180 top
C641 "470pF" "CAP 0402/1005 RF" 217.555,41.359 r180 top
C642 "56pF" "CAP 0402/1005 RF" 209.451,41.359 r0 top
C643 "8.2nF" "CAP 0402/1005 RF" 219.162,40.694 r270 top
C644 "820pF" "CAP 0402/1005 RF" 207.935,40.749 r270 top
C645 "1.2nF" "CAP 0402/1005 RF" 164.256,62.307 r180 top
C646 "1.2nF" "CAP 0402/1005 RF" 167.741,62.307 r0 top
C647 "47nF" "CAP 0402/1005 RF" 161.843,39.015 r0 top
C648 "47nF" "CAP 0402/1005 RF" 170.124,38.803 r180 top
C649 "100nF" "CAP 0402/1005 RF" 410.883,27.889 r90 top
C650 "180pF" "CAP 0402/1005 RF" 170.124,37.89 r180 top
C651 "100nF" "CAP 0402/1005 RF" 404.025,27.889 r90 top
C652 "2.2nF" "CAP 0402/1005 RF" 171.666,37.4 r270 top
C653 "100nF" "CAP 0402/1005 RF" 396.659,27.889 r90 top
C654 "100nF" "CAP 0402/1005 RF" 173.978,134.224 r90 top
C655 "5.6nF" "CAP 0402/1005 RF" 186.721,131.98 r270 top
C656 "5.6nF" "CAP 0402/1005 RF" 187.116,126.745 r270 top
C657 "5.6nF" "CAP 0402/1005 RF" 186.869,121.628 r270 top
C658 "100nF" "CAP 0402/1005 RF" 472.338,29.388 r0 top
C659 "4.7uF" "CAP 0603/1608 RF" 419.24,29.21 r0 top
C660 "100nF" "CAP 0402/1005 RF" 423.227,29.388 r0 top
C661 "4.7uF" "CAP 0603/1608 RF" 404.762,29.21 r0 top
C662 "100nF" "CAP 0402/1005 RF" 408.749,29.388 r0 top
C663 "27pF" "CAP 0402/1005 RF" 395.796,29.388 r0 top
C664 "27pF" "CAP 0402/1005 RF" 400.113,29.388 r0 top
C665 "100nF" "CAP 0402/1005 RF" 365.57,29.388 r0 top
C666 "100nF" "CAP 0402/1005 RF" 369.887,29.388 r0 top
C667 "100nF" "CAP 0402/1005 RF" 374.205,29.388 r0 top
C668 "100nF" "CAP 0402/1005 RF" 378.524,29.388 r0 top
C669 "100nF" "CAP 0402/1005 RF" 382.841,29.388 r0 top
C670 "100nF" "CAP 0402/1005 RF" 387.159,29.388 r0 top
C671 "100nF" "CAP 0402/1005 RF" 391.477,29.388 r0 top
C672 "Capacitor_1210" CAPC3326X17L 403.019,54.508 r0 top
C673 "100nF" "CAP 0402/1005 RF" 356.734,29.437 r0 top
C674 "4.7uF" "CAP 0402/1005 RF" 159.306,147.662 r180 top
C675 "4.7uF" "CAP 0402/1005 RF" 157.587,152.512 r270 top
C676 "4.7uF" "CAP 0402/1005 RF" 164.589,151.15 r270 top
C677 "100nF" "CAP 0402/1005 RF" 389.293,27.889 r90 top
C678 "100uF" "CAP 1206/3216" 423.621,49.86 r0 top
C679 "100uF" "CAP 1206/3216" 423.342,52.4 r0 top
C680 "1uF" "CAP 0402/1005 RF" 361.251,41.491 r0 top
C693 "470nF" "CAP 0402/1005 RF" 59.589,77.52 r90 top
C694 "4.7uF" "CAP 0603/1608 RF" 86.59,76.065 r270 top
C695 "10uF" "CAP 0805/2012 RF" 79.463,76.068 r270 top
C696 "10uF" "CAP 0805/2012 RF" 83.04,76.069 r270 top
C697 "10uF" "CAP 0805/2012 RF" 81.218,76.069 r270 top
C698 "10uF" "CAP 0805/2012 RF" 77.658,76.065 r270 top
C699 "10uF" "CAP 0805/2012 RF" 84.868,76.065 r270 top
C700 "1uF" "CAP 0402/1005 RF" 87.728,76.065 r270 top
C701 "12nF" "CAP 0402/1005 RF" 49.574,77.884 r180 top
C702 "36pF" "CAP 0402/1005 RF" 48.659,79.42 r0 top
C703 "15nF" "CAP 0402/1005 RF" 52.778,77.442 r90 top
C704 "1uF" "CAP 0603/1608 RF" 46.685,85.014 r90 top
C705 "10uF" "CAP 0603/1608 RF" 302.427,172.155 r90 top
C706 "10nF" "CAP 0201/0603 RF" 301.053,175.397 r0 top
C707 "10uF" "CAP 0805/2012 RF" 292.356,170.733 r90 top
C708 "10uF" "CAP 0805/2012 RF" 294.076,170.733 r90 top
C709 "10uF" "CAP 0603/1608 RF" 301.102,165.803 r180 top
C710 "10nF" "CAP 0201/0603 RF" 301.053,168.063 r180 top
C711 "100nF" "CAP 0402/1005 RF" 297.752,167.803 r90 top
C712 "100nF" "CAP 0402/1005 RF" 297.752,175.18 r270 top
C713 "100nF" "CAP 0402/1005 RF" 248.384,150.119 r270 top
C714 "330nF" "CAP 0603/1608 RF" 248.376,152.782 r90 top
C715 "100nF" "CAP 0402/1005 RF" 382.168,27.889 r90 top
C716 "100nF" "CAP 0402/1005 RF" 375.056,27.889 r90 top
C717 "100nF" "CAP 0402/1005 RF" 367.944,27.889 r90 top
C718 "100nF" "CAP 0402/1005 RF" 356.464,27.352 r90 top
C719 "1nF" "CAP 0201/0603 RF" 161.718,153.027 r180 top
C720 "1uF" "CAP 0402/1005 RF" 213.741,211.107 r270 top
C721 "1uF" "CAP 0402/1005 RF" 214.655,211.107 r270 top
C722 "1uF" "CAP 0402/1005 RF" 217.151,212.008 r0 top
C723 "1uF" "CAP 0402/1005 RF" 220.364,212.558 r180 top
C724 "10nF" "CAP 0201/0603 RF" 388.645,29.997 r90 top
C725 "10nF" "CAP 0201/0603 RF" 381.279,29.997 r90 top
C726 "10nF" "CAP 0201/0603 RF" 373.913,29.997 r90 top
C727 "10nF" "CAP 0201/0603 RF" 366.547,29.997 r90 top
C728 "100nF" "CAP 0402/1005 RF" 101.516,194.212 r180 bottom
C729 "100nF" "CAP 0402/1005 RF" 96.278,197.904 r270 bottom
C730 "100nF" "CAP 0402/1005 RF" 97.278,197.904 r270 bottom
C731 "2.2uF" "CAP 0402/1005 RF" 101.516,193.329 r180 bottom
C732 "100nF" "CAP 0402/1005 RF" 95.154,197.904 r270 bottom
C733 "1uF" "CAP 0402/1005 RF" 48.234,201.394 r270 top
C734 "1uF" "CAP 0402/1005 RF" 44.348,200.729 r90 top
C735 "100nF" "CAP 0402/1005 RF" 95.053,200.491 r270 bottom
C736 "9pF" "CAP 0201/0603 RF" 96.124,198.327 r0 top
C737 "9pF" "CAP 0201/0603 RF" 101.401,199.944 r180 top
C738 "6TPE680MI" "CAP POL 2917/7343" 538.734,141.097 r90 top
C739 "100uF" "CAP 1210/3225 - 1MM" 545.236,143.231 r90 top
C740 "4.7uF" "CAP 0402/1005 RF" 551.434,144.729 r90 top
C741 "4.7uF" "CAP 0402/1005 RF" 558.8,144.729 r90 top
C742 "100uF" "CAP 1210/3225 - 1MM" 523.113,143.231 r90 top
C743 "4.7uF" "CAP 0402/1005 RF" 529.311,144.729 r90 top
C744 "47uF" "CAP 1206/3216 - 0.8MM" 485.775,143.231 r90 top
C745 "4.7uF" "CAP 0402/1005 RF" 492.455,144.729 r90 top
C746 "4.7uF" "CAP 0402/1005 RF" 499.821,144.729 r90 top
C747 "100uF" "CAP 1210/3225 - 1MM" 508.381,143.231 r90 top
C748 "4.7uF" "CAP 0402/1005 RF" 514.579,144.729 r90 top
C749 "47uF" "CAP 1206/3216 - 0.8MM" 434.721,143.231 r90 top
C750 "4.7uF" "CAP 0402/1005 RF" 441.401,144.729 r90 top
C751 "100uF" "CAP 1210/3225 - 1MM" 450.698,143.993 r0 top
C752 "4.7uF" "CAP 0402/1005 RF" 455.625,144.729 r90 top
C753 "100uF" "CAP 1210/3225 - 1MM" 464.16,143.231 r90 top
C754 "4.7uF" "CAP 0402/1005 RF" 470.357,144.729 r90 top
C755 "4.7uF" "CAP 0402/1005 RF" 477.723,144.729 r90 top
C756 "47uF" "CAP 1206/3216 - 0.8MM" 412.598,143.231 r90 top
C757 "100uF" "CAP 1210/3225 - 1MM" 420.472,143.231 r90 top
C758 "4.7uF" "CAP 0402/1005 RF" 426.669,144.729 r90 top
C759 "47uF" "CAP 1206/3216 - 0.8MM" 391.008,143.231 r90 top
C760 "100uF" "CAP 1210/3225 - 1MM" 398.856,143.231 r90 top
C761 "4.7uF" "CAP 0402/1005 RF" 405.054,144.729 r90 top
C762 "100uF" "CAP 1210/3225 - 1MM" 362.001,143.231 r90 top
C763 "4.7uF" "CAP 0402/1005 RF" 368.224,144.729 r90 top
C764 "100uF" "CAP 1210/3225 - 1MM" 376.758,143.231 r90 top
C765 "4.7uF" "CAP 0402/1005 RF" 382.956,144.729 r90 top
C766 "22uF" "CAP 1210/3225 - 1MM" 85.519,29.46 r270 top
C767 "22uF" "CAP 1210/3225 - 1MM" 82.051,29.46 r270 top
C768 "22uF" "CAP 1210/3225 - 1MM" 78.611,29.46 r270 top
C769 "22uF" "CAP 1210/3225 - 1MM" 75.207,29.46 r270 top
C770 "100nF" "CAP 0402/1005 RF" 75.872,33.255 r270 top
C771 "100nF" "CAP 0402/1005 RF" 74.865,33.255 r270 top
C772 "100nF" "CAP 0402/1005 RF" 73.958,33.255 r270 top
C773 "100nF" "CAP 0402/1005 RF" 73.027,33.255 r270 top
C774 "10uF" "CAP 0805/2012 RF" 88.682,33.471 r270 top
C775 "10uF" "CAP 0805/2012 RF" 86.869,33.471 r270 top
C776 "10uF" "CAP 0805/2012 RF" 85.046,33.471 r270 top
C777 "10uF" "CAP 0805/2012 RF" 83.301,33.47 r270 top
C778 "4.7uF" "CAP 0805/2012 RF" 81.487,33.471 r270 top
C779 "4.7uF" "CAP 0805/2012 RF" 79.678,33.471 r270 top
C780 "4.7uF" "CAP 0805/2012 RF" 77.783,33.471 r270 top
C781 "4.7uF" "CAP 0805/2012 RF" 72.627,29.501 r90 top
C782 "4.7uF" "CAP 0402/1005 RF" 405.054,119.177 r90 top
C783 "100nF" "CAP 0402/1005 RF" 412.42,119.177 r90 top
C784 "4.7uF" "CAP 0402/1005 RF" 390.322,119.177 r90 top
C785 "100nF" "CAP 0402/1005 RF" 397.688,119.177 r90 top
C786 "4.7uF" "CAP 0402/1005 RF" 375.564,119.177 r90 top
C787 "100nF" "CAP 0402/1005 RF" 382.93,119.177 r90 top
C788 "4.7uF" "CAP 0402/1005 RF" 360.832,119.177 r90 top
C789 "100nF" "CAP 0402/1005 RF" 368.198,119.177 r90 top
C790 "100nF" "CAP 0402/1005 RF" 415.29,76.149 r90 top
C791 "100nF" "CAP 0402/1005 RF" 491.49,56.363 r90 top
C792 "100nF" "CAP 0402/1005 RF" 369.621,56.363 r90 top
D1 "SLVU2.8-4BTG TVS Array" SLVU2.8-4 64.516,106.68 r0 bottom
D2 "SLVU2.8-4BTG TVS Array" SLVU2.8-4 64.389,112.649 r0 bottom
D3 "DF01S2" "DF005S2 - DF10S2" 41.986,91.694 r90 top
D4 "DF01S2" "DF005S2 - DF10S2" 32.233,91.694 r90 top
D5 "LTST-C190GKT" "LED 0603/1608 GREEN" 36.761,327.152 r90 top
D6 "LTST-C190GKT" "LED 0603/1608 GREEN" 34.729,327.406 r90 top
D7 "LTST-C190GKT" "LED 0603/1608 GREEN" 39.159,327.152 r90 top
D8 "LTST-C190GKT" "LED 0603/1608 GREEN" 44.254,327.025 r90 top
D9 "LTST-C190GKT" "LED 0603/1608 GREEN" 41.841,327.025 r270 top
D10 "LTST-C190GKT" "LED 0603/1608 GREEN" 361.899,113.386 r0 top
D11 "BAT54T1G" BAT54T1G 63.275,314.483 r90 top
D12 "BAT54T1G" BAT54T1G 60.856,314.483 r90 top
D13 "TPD2EUSB30DRTR" TPD2EUSB30 43.587,211.733 r0 top
D14 "TPD4EUSB30DQAR" TPD4EUSB30 46.096,211.733 r0 top
D15 "TPD2EUSB30DRTR" TPD2EUSB30 330.505,48.909 r0 top
D16 "MBRM140T3" "CASE 457" 235.57,246.422 r0 top
D17 "MBRM140T3" "CASE 457" 235.57,250.308 r0 top
D18 "MBRM140T3" "CASE 457" 238.87,254.678 r0 top
D19 "MBRM140T3" "CASE 457" 238.87,241.471 r0 top
D20 "S1M-13-F" S1M-13-F 445.567,73.889 r90 top
D21 "S1M-13-F" S1M-13-F 404.787,73.889 r90 top
D22 "S1M-13-F" S1M-13-F 382.676,73.889 r90 top
D23 "S1M-13-F" S1M-13-F 378.13,73.889 r90 top
D26 "DFLS1100-7" DFLS1100 59.128,79.555 r180 top
D27 "DFLS1100-7" DFLS1100 48.733,86.491 r270 top
D28 "BAS40-04-TP" BAS40-04-TP 395.376,201.625 r0 top
FB1_PCIE0 "Ferrite Chip" "FER 0603/1608" 97.917,246.039 r90 top (schematic designator FB1)
FB1_PCIE1 "Ferrite Chip" "FER 0603/1608" 288.671,145.119 r180 top (schematic designator FB1)
FB1_PCIE2 "Ferrite Chip" "FER 0603/1608" 134.376,146.732 r0 top (schematic designator FB1)
FB1_PCIE3 "Ferrite Chip" "FER 0603/1608" 136.906,121.158 r180 top (schematic designator FB1)
FB1_PCIE4 "Ferrite Chip" "FER 0603/1608" 300.177,83.566 r180 top (schematic designator FB1)
FB2 "220Ohm" "FER 0603/1608" 98.044,154.496 r90 top
FB3 "220Ohm" "FER 0603/1608" 441.418,347.004 r270 top
FB4 "220Ohm" "FER 0603/1608" 99.822,154.496 r90 top
FB5 "220Ohm" "FER 0603/1608" 436.868,331.523 r90 top
FB6 "220Ohm" "FER 0603/1608" 446.056,343.592 r180 top
FB7 "220Ohm" "FER 0603/1608" 473.511,406.18 r90 top
FB8 "220R" "FER 0603/1608" 323.363,171.471 r0 top
FB9 "220R" "FER 0603/1608" 343.792,183.939 r180 top
FB10 "220R" "FER 0603/1608" 335.8,171.843 r90 top
FB11 "220R" "FER 0603/1608" 318.755,184.158 r0 top
FB12 "220R" "FER 0603/1608" 331.727,167.474 r90 top
FB13 "220R" "FER 0603/1608" 321.44,190.813 r270 top
FB14 "220R" "FER 0603/1608" 327.453,167.474 r90 top
FB15 "220R" "FER 0603/1608" 332.235,195.073 r270 top
FB16 "220R" "FER 0603/1608" 343.792,179.264 r180 top
FB17 "220R" "FER 0603/1608" 328.453,195.073 r270 top
FB18 "220R" "FER 0603/1608" 343.792,181.611 r180 top
FB19 "220R" "FER 0603/1608" 343.792,176.912 r180 top
FB20 "220R" "FER 0603/1608" 318.733,180.764 r0 top
FB21 "220R" "FER 0603/1608" 329.453,167.474 r90 top
FB22 "220R" "FER 0603/1608" 318.733,178.264 r0 top
FB23 "Ferrite Chip" "FER 0603/1608" 353.704,65.372 r0 top
FB24 "Ferrite Chip" "FER 0603/1608" 426.404,359.537 r0 top
FB25 "Ferrite Chip" "FER 0603/1608" 84.963,216.662 r270 top
FB26 "220R" "FER 0603/1608" 42.011,208.157 r180 top
FB27 "220R" "FER 0603/1608" 41.059,218.483 r270 top
FB28 "220R" "FER 0603/1608" 29.891,224.808 r90 top
FB29 "220R" "FER 0603/1608" 76.251,85.166 r90 top
FB31 "220R" "FER 0603/1608" 331.26,46.401 r180 top
FB32 "220R" "FER 0603/1608" 331.267,51.901 r180 top
FB33 "120R" "FER 0603/1608" 294.485,198.46 r270 top
FB34 "330R" "FER 0603/1608" 418.907,343.927 r180 top
FB35 "220Ohm" "FER 0603/1608" 361.086,68.047 r90 top
FB36 "220R" "FER 0603/1608" 336.58,165.917 r270 top
FB37 "220R" "FER 0603/1608" 322.084,167.184 r270 top
FB38 "600R" "FER 0805/2012" 410.553,73.901 r90 top
FB39 "600R" "FER 0805/2012" 396.075,73.901 r90 top
FB40 "600R" "FER 0805/2012" 390.233,73.901 r90 top
FB41 "600R" "FER 0805/2012" 375.755,73.901 r90 top
FB42 "120R" "FER 0603/1608" 369.71,74.181 r90 top
FB43 "220R" "FER 0603/1608" 427.368,28.423 r90 top
FB44 "220R" "FER 0603/1608" 412.89,28.423 r90 top
FB45 "120R" "FER 0603/1608" 157.587,150.162 r90 top
J1_PCIE0 "Key M" "M.2 KEY M" 215.866,102.658 r90 bottom (schematic designator J1)
J1_PCIE2 "Key M" "M.2 KEY M" 83.795,224.954 r0 bottom (schematic designator J1)
J1_PCIE4 "Key M" "M.2 KEY M" 292.557,209.821 r180 bottom (schematic designator J1)
J2 "1909763-1" TECO-1909763-1_V 91.773,143.213 r0 top
J3 "1909763-1" TECO-1909763-1_V 96.348,143.213 r0 top
J4 "1909763-1" TECO-1909763-1_V 95.987,131.884 r0 top
J5 "1909763-1" TECO-1909763-1_V 90.932,131.884 r0 top
J6 "5-1814832-1" TECO-5-1814832-1_V 405.058,409.321 r90 bottom
J7 "5-1814832-1" TECO-5-1814832-1_V 405.058,400.304 r90 bottom
J8 "5-1814832-1" TECO-5-1814832-1_V 456.26,299.39 r180 bottom
J9 "5-1814832-1" TECO-5-1814832-1_V 465.277,299.39 r180 bottom
J10 "5-1814832-1" TECO-5-1814832-1_V 418.313,300.236 r180 bottom
J11 "5-1814832-1" TECO-5-1814832-1_V 427.711,300.236 r180 bottom
J12 "I2C_0Master" "MOLEX KK 0022272021" 158.496,264.414 r0 top
J13 "I2C1_Master" "MOLEX KK 0022272021" 102.532,218.313 r270 top
J14 "7 Pin" "JST XH B7B-XH-A" 62.731,214.528 r180 bottom
J15 "GPIO0_12" "MOLEX KK 0022272021" 159.258,247.269 r0 top
J16 "GPIO0_23" "MOLEX KK 0022272021" 140.843,249.301 r0 top
J17 "GPIO1_38" "MOLEX KK 0022272021" 128.397,256.921 r0 top
J18 "7 Pin" "JST XH B7B-XH-A" 579.356,6.706 r0 bottom
J19 "GPIO2_66" "MOLEX KK 0022272021" 135.509,257.302 r0 top
J20 "GPIO2_70" "MOLEX KK 0022272021" 143.002,257.556 r0 top
J21 "GPIO2_72" "MOLEX KK 0022272021" 150.114,254.254 r0 top
J22 "GPIO2_73" "MOLEX KK 0022272021" 157.734,255.905 r0 top
J23 "GPIO2_74" "MOLEX KK 0022272021" 117.475,225.933 r0 top
J24 "GPIO2_75" "MOLEX KK 0022272021" 109.347,226.187 r0 top
J25 "SPI1" "JST XH B4B-XH-A" 98.171,234.188 r90 top
J26 "5-1814832-1" TECO-5-1814832-1_V 207.234,159.385 r90 bottom
J27 "Key M-SATA CHINA" "M.2 KEY M - NVMe" 136.776,174.6 r270 bottom
J28 "693071020811" 693071020811 118.999,209.931 r90 bottom
J31 "SFP Connector" 2007132 393.421,30.556 r90 top
J32 "1703820001" 1703820001 361.671,101.067 r0 top
J33 "1703820001" 1703820001 361.671,119.71 r0 top
J34 "1703820001" 1703820001 361.671,138.354 r0 top
J35 "1703820001" 1703820001 361.671,156.997 r0 top
L1 "NRS4018T4R7MDGJV" NRS8040 72.523,129.469 r0 top
L2 "NRS4018T4R7MDGJV" NRS8040 66.249,129.469 r0 top
L3 "NRS4018T4R7MDGJV" NRS8040 91.376,155.385 r0 top
L4 "NRS4018T4R7MDGJV" NRS8040 85.103,155.385 r0 top
L5 "NRS4018T4R7MDGJV" NRS8040 87.298,173.643 r0 top
L6 "NRS4018T4R7MDGJV" NRS8040 81.024,173.643 r0 top
L7 "NRS4018T4R7MDGJV" NRS8040 87.298,182.165 r0 top
L8 "NRS4018T4R7MDGJV" NRS8040 81.024,182.165 r0 top
L9 "MGV0605R22M-10" MGV0605 118.066,71.501 r90 top
L10 "MGV0605R22M-10" MGV0605 126.914,71.526 r90 top
L11 "MGV10041R2M-10" "MGV1004 Series" 204.133,67.314 r90 top
L12 "744373560068" 744373560068 222.802,66.258 r90 top
L13 "CDRH5D28-8R2" CDRH5D28 225.965,244.934 r270 top
L15 "Inductance" FB0603 244.749,253.225 r0 top
L16 "CDRH5D28-4R2" CDRH5D28 225.965,251.976 r90 top
L17 "CDRH5D28-8R2" CDRH5D28 230.607,259.08 r90 top
L18 "CDRH4D28NP-3R3NC" CDRH4D28NP 230.914,238.351 r270 top
L19 "3.3uH, 13.8A" WE-CHSA_1011 155.203,63.097 r90 top
L20 "1.5 uH, 16.5 A" WE-HCC_8070 175.434,62.307 r90 top
L22 "SRP1265A-220M" SRP1265A-220M 67.695,70.552 r0 top
MP1_PCIE0 "M2x2.5mm" 9774025243 363.195,29.82 r90 top (schematic designator MP1)
MP1_PCIE1 "M2x2.5mm" 9774025243 363.195,39.903 r90 top (schematic designator MP1)
MP1_PCIE2 "M2x2.5mm" 9774025243 363.195,49.987 r90 top (schematic designator MP1)
MP1_PCIE3 "M2x2.5mm" 9774025243 363.195,60.071 r90 top (schematic designator MP1)
MP1_PCIE4 "M2x2.5mm" 9774025243 394.056,180.504 r90 top (schematic designator MP1)
MP2_PCIE0 "M2x2.5mm" 9774025243 377.927,29.82 r90 top (schematic designator MP2)
MP2_PCIE1 "M2x2.5mm" 9774025243 377.419,39.903 r90 top (schematic designator MP2)
MP2_PCIE2 "M2x2.5mm" 9774025243 377.927,49.987 r90 top (schematic designator MP2)
MP2_PCIE3 "M2x2.5mm" 9774025243 377.927,60.071 r90 top (schematic designator MP2)
MP2_PCIE4 "M2x2.5mm" 9774025243 377.927,70.155 r90 top (schematic designator MP2)
MP3_PCIE0 "M2x2.5mm" 9774025243 392.659,29.82 r90 top (schematic designator MP3)
MP3_PCIE1 "M2x2.5mm" 9774025243 391.643,39.903 r90 top (schematic designator MP3)
MP3_PCIE2 "M2x2.5mm" 9774025243 392.659,49.987 r90 top (schematic designator MP3)
MP3_PCIE3 "M2x2.5mm" 9774025243 392.659,60.071 r90 top (schematic designator MP3)
MP3_PCIE4 "M2x2.5mm" 9774025243 392.659,70.155 r90 top (schematic designator MP3)
P1 "Header 3" HDR1X3 1.37,348.539 r90 top
P2 "Header 4" HDR1X4 236.601,227.711 r270 top
P3 "Header 2" HDR1X2 66.571,312.852 r90 top
P4 "Header 2" HDR1X2 68.476,312.217 r90 top
P5 "Header 2" HDR1X2 71.397,311.836 r90 top
P6 "640456-2" TECO-640456-2_V 100.94,122.453 r90 top
P7 "Plug" PIN1#1 30.201,37.338 r90 top
P8 "Plug" PIN1#2 30.201,34.188 r90 top
P9 "Plug" PIN1#3 30.16,45.116 r90 top
P10 "Plug" PIN1#2 30.16,42.222 r90 top
P11 "Header 2" HDR1X2 366.014,95.047 r90 top
P12 "Header 7X2" HDR2X7 386.207,37.948 r90 top
P13 "Header 3" HDR1X3 370.332,178.714 r90 top
R1 "0R" "RES 0402/1005 RF" 379.959,41.046 r0 top
R2 "0R" "RES 0402/1005 RF" 375.641,41.046 r0 top
R3_I2C_Bridge "1kR" "RES 0402/1005 RF" 100.35,266.377 r90 top (schematic designator R3)
R3_I2C_Bridge_2 "1kR" "RES 0402/1005 RF" 740.816,46.787 r90 top (schematic designator R3)
R3_I2C_Bridge_3 "1kR" "RES 0402/1005 RF" 72.782,165.875 r90 top (schematic designator R3)
R4_I2C_Bridge "1kR" "RES 0402/1005 RF" 101.35,266.377 r90 top (schematic designator R4)
R4_I2C_Bridge_2 "1kR" "RES 0402/1005 RF" 717.194,46.787 r90 top (schematic designator R4)
R4_I2C_Bridge_3 "1kR" "RES 0402/1005 RF" 73.859,165.875 r90 top (schematic designator R4)
R5_I2C_Bridge "1kR" "RES 0402/1005 RF" 102.425,266.377 r90 top (schematic designator R5)
R5_I2C_Bridge_2 "1kR" "RES 0402/1005 RF" 693.572,46.787 r90 top (schematic designator R5)
R5_I2C_Bridge_3 "1kR" "RES 0402/1005 RF" 74.937,165.875 r90 top (schematic designator R5)
R6_I2C_Bridge "1kR" "RES 0402/1005 RF" 103.485,266.377 r90 top (schematic designator R6)
R6_I2C_Bridge_2 "1kR" "RES 0402/1005 RF" 669.95,46.787 r90 top (schematic designator R6)
R6_I2C_Bridge_3 "1kR" "RES 0402/1005 RF" 76.014,165.875 r90 top (schematic designator R6)
R7_I2C_Bridge "1kR" "RES 0402/1005 RF" 104.558,266.377 r90 top (schematic designator R7)
R7_I2C_Bridge_2 "1kR" "RES 0402/1005 RF" 646.328,46.787 r90 top (schematic designator R7)
R7_I2C_Bridge_3 "1kR" "RES 0402/1005 RF" 77.092,165.875 r90 top (schematic designator R7)
R8_I2C_Bridge "1kR" "RES 0402/1005 RF" 106.426,264.033 r0 top (schematic designator R8)
R8_I2C_Bridge_2 "1kR" "RES 0402/1005 RF" 622.706,46.787 r90 top (schematic designator R8)
R8_I2C_Bridge_3 "1kR" "RES 0402/1005 RF" 79.952,164.169 r0 top (schematic designator R8)
R9_I2C_Bridge "1kR" "RES 0402/1005 RF" 106.426,262.978 r0 top (schematic designator R9)
R9_I2C_Bridge_2 "1kR" "RES 0402/1005 RF" 599.11,46.787 r90 top (schematic designator R9)
R9_I2C_Bridge_3 "1kR" "RES 0402/1005 RF" 79.952,163.195 r0 top (schematic designator R9)
R10_I2C_Bridge "1kR" "RES 0402/1005 RF" 106.426,261.922 r0 top (schematic designator R10)
R10_I2C_Bridge_2 "1kR" "RES 0402/1005 RF" 574.218,46.787 r90 top (schematic designator R10)
R10_I2C_Bridge_3 "1kR" "RES 0402/1005 RF" 79.952,162.221 r0 top (schematic designator R10)
R11 "10kR" "RES 0402/1005 RF" 67.052,39.15 r90 top
R12 "95.3kR" "RES 0402/1005 RF" 65.999,55.624 r180 top
R13 "10kR" "RES 0402/1005 RF" 66.879,50.661 r90 top
R14 "0mR" "RES 0402/1005 RF" 175.712,102.141 r90 bottom
R15 "95.3kR" "RES 0402/1005 RF" 66.181,44.35 r180 top
R16 "0mR" "RES 0402/1005 RF" 176.728,102.141 r90 bottom
R17 "95.3kR" "RES 0402/1005 RF" 69.193,44.693 r0 top
R18 "24.9kR" "RES 0402/1005 RF" 67.96,39.15 r90 top
R19 "4.87kR" "RES 0402/1005 RF" 67.512,56.124 r270 top
R20 "95.3kR" "RES 0402/1005 RF" 69.012,55.595 r0 top
R21 "24.9kR" "RES 0402/1005 RF" 67.854,50.661 r90 top
R22 "0mR" "RES 0402/1005 RF" 174.687,102.141 r90 bottom
R23 "4.87kR" "RES 0402/1005 RF" 67.56,44.843 r270 top
R24 "0mR" "RES 0402/1005 RF" 173.68,102.141 r90 bottom
R25 "4.87kR" "RES 0402/1005 RF" 69.193,45.643 r180 top
R26 "4.87kR" "RES 0402/1005 RF" 69.012,56.524 r180 top
R27 "1.02kR" "RES 0402/1005 RF" 40.589,62.001 r270 top
R28 "1.02kR" "RES 0402/1005 RF" 35.916,60.02 r270 top
R29 "10kR" "RES 0402/1005 RF" 47.048,62.763 r90 top
R30 "10kR" "RES 0402/1005 RF" 45.322,63.017 r90 top
R31 "39.2R" "RES 0402/1005 RF" 186.039,255.482 r90 top
R32 "39.2R" "RES 0402/1005 RF" 186.039,259.546 r90 top
R33 "39.2R" "RES 0402/1005 RF" 175.244,244.502 r270 top
R34 "39.2R" "RES 0402/1005 RF" 177.303,240.565 r270 top
R35 "39.2R" "RES 0402/1005 RF" 184.985,255.482 r90 top
R36 "39.2R" "RES 0402/1005 RF" 187.055,259.546 r90 top
R37 "39.2R" "RES 0402/1005 RF" 176.26,244.502 r270 top
R38 "39.2R" "RES 0402/1005 RF" 189.087,259.546 r90 top
R39 "39.2R" "RES 0402/1005 RF" 187.055,255.482 r90 top
R40 "39.2R" "RES 0402/1005 RF" 189.087,255.482 r90 top
R41 "39.2R" "RES 0402/1005 RF" 176.26,240.565 r270 top
R42 "39.2R" "RES 0402/1005 RF" 184.007,255.482 r90 top
R43 "39.2R" "RES 0402/1005 RF" 185.023,259.546 r90 top
R44 "39.2R" "RES 0402/1005 RF" 190.103,255.482 r90 top
R45 "39.2R" "RES 0402/1005 RF" 175.244,240.565 r270 top
R46 "39.2R" "RES 0402/1005 RF" 179.308,244.502 r270 top
R47 "39.2R" "RES 0402/1005 RF" 184.134,259.546 r90 top
R48 "39.2R" "RES 0402/1005 RF" 174.228,244.502 r270 top
R49 "39.2R" "RES 0402/1005 RF" 188.071,255.482 r90 top
R50 "39.2R" "RES 0402/1005 RF" 183.245,259.546 r90 top
R51 "39.2R" "RES 0402/1005 RF" 177.303,244.502 r270 top
R52 "36R" "RES 0402/1005 RF" 179.435,240.565 r270 top
R53 "39.2R" "RES 0402/1005 RF" 174.228,240.565 r270 top
R54 "36R" "RES 0402/1005 RF" 180.324,244.502 r270 top
R55 "39.2R" "RES 0402/1005 RF" 188.071,259.546 r90 top
R56 "499R" "RES 0402/1005 RF" 176.641,234.977 r270 top
R57 "39.2R" "RES 0402/1005 RF" 178.292,244.502 r270 top
R58 "4.7kR" "RES 0402/1005 RF" 175.244,234.977 r270 top
R59 "39.2R" "RES 0402/1005 RF" 178.292,240.565 r270 top
R60 "1kR" "RES 0402/1005 RF" 184.007,263.356 r180 top
R61 "240R" "RES 0402/1005 RF" 202.147,264.901 r90 top
R62 "240R" "RES 0402/1005 RF" 201.697,252.201 r90 top
R63 "240R" "RES 0402/1005 RF" 202.216,240.263 r90 top
R64 "240R" "RES 0402/1005 RF" 210.579,240.899 r90 top
R65 "4.7kR" "RES 0402/1005 RF" 50.154,141.54 r180 top
R66 "4.7kR" "RES 0402/1005 RF" 50.154,142.621 r180 top
R67 "4.7kR" "RES 0402/1005 RF" 50.154,139.508 r180 top
R68 "4.7kR" "RES 0402/1005 RF" 50.154,140.524 r180 top
R69 "100R" "RES 0402/1005 RF" 45.847,197.485 r90 top
R70 "100R" "RES 0402/1005 RF" 51.689,197.485 r90 top
R71 "0R" "RES 0402/1005 RF" 46.863,146.05 r180 top
R72 "0R" "RES 0402/1005 RF" 46.863,145.034 r180 top
R73 "0R" "RES 0402/1005 RF" 49.025,146.05 r180 top
R74 "0R" "RES 0402/1005 RF" 49.025,145.034 r180 top
R75 "100R" "RES 0402/1005 RF" 93.998,140.075 r180 top
R76 "100R" "RES 0402/1005 RF" 93.548,128.342 r0 top
R77 "7.5kR" "RES 0402/1005 RF" 444.144,347.285 r90 top
R78 "100R" "RES 0402/1005 RF" 410.862,405.003 r270 top
R79 "100R" "RES 0402/1005 RF" 461.086,304.978 r0 top
R80 "100R" "RES 0402/1005 RF" 422.827,306.078 r0 top
R81 "100R" "RES 0402/1005 RF" 439.318,347.336 r180 top
R82 "100R" "RES 0402/1005 RF" 194.818,169.418 r90 top
R83 "4.7kR" "RES 0402/1005 RF" 108.077,219.701 r0 top
R84 "4.7kR" "RES 0402/1005 RF" 108.331,216.281 r0 top
R85 "4.7kR" "RES 0402/1005 RF" 108.077,218.821 r0 top
R86 "4.7kR" "RES 0402/1005 RF" 108.331,217.424 r0 top
R87 "30R" "RES 0402/1005 RF" 138.049,205.562 r180 bottom
R88 "30R" "RES 0402/1005 RF" 138.049,203.479 r180 bottom
R89 "30R" "RES 0402/1005 RF" 138.049,210.769 r180 bottom
R90 "30R" "RES 0402/1005 RF" 138.049,208.686 r180 bottom
R91 "0R" "RES 0402/1005 RF" 138.049,209.728 r180 bottom
R92 "0R" "RES 0402/1005 RF" 138.049,211.811 r180 bottom
R93 "0R" "RES 0402/1005 RF" 138.049,212.852 r180 bottom
R94 "0R" "RES 0402/1005 RF" 138.049,202.438 r180 bottom
R95 "30R" "RES 0402/1005 RF" 138.049,204.521 r180 bottom
R96 "30R" "RES 0402/1005 RF" 138.049,207.645 r180 bottom
R97 "4.7kR" "RES 0402/1005 RF" 138.049,206.604 r180 bottom
R98 "4.7kR" "RES 0402/1005 RF" 98.954,172.085 r180 bottom
R99 "4.7kR" "RES 0402/1005 RF" 360.883,61.417 r90 top
R100 "Resistance" "RES 0402/1005 RF" 320.421,311.404 r0 top
R101 "30R" "RES 0402/1005 RF" 133.096,197.739 r180 top
R102 "30R" "RES 0402/1005 RF" 133.096,195.707 r180 top
R103 "30R" "RES 0402/1005 RF" 133.096,193.675 r180 top
R104 "30R" "RES 0402/1005 RF" 133.096,191.643 r180 top
R105 "30R" "RES 0402/1005 RF" 133.096,196.723 r180 top
R106 "1kR" "RES 0402/1005 RF" 4.046,348.539 r180 top
R107 "30R" "RES 0402/1005 RF" 133.096,194.691 r180 top
R108 "30R" "RES 0402/1005 RF" 133.096,192.659 r180 top
R109 "1kR" "RES 0402/1005 RF" 142.494,330.581 r0 top
R110 "30R" "RES 0402/1005 RF" 133.096,198.755 r180 top
R111 "30R" "RES 0402/1005 RF" 133.096,190.602 r180 top
R112 "30R" "RES 0402/1005 RF" 133.096,189.611 r180 top
R113 "34.8kR" "RES 0402/1005 RF" 251.788,249.461 r270 top
R114 "10kR" "RES 0402/1005 RF" 252.738,249.468 r90 top
R115 "30R" "RES 0402/1005 RF" 94.953,204.77 r0 top
R116 "30R" "RES 0402/1005 RF" 93.403,197.866 r0 top
R117 "30R" "RES 0402/1005 RF" 91.313,197.866 r0 top
R118 "30R" "RES 0402/1005 RF" 86.995,197.866 r0 top
R119 "30R" "RES 0402/1005 RF" 94.953,205.883 r0 top
R120 "30R" "RES 0402/1005 RF" 93.853,199.644 r0 top
R121 "30R" "RES 0402/1005 RF" 89.535,199.644 r0 top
